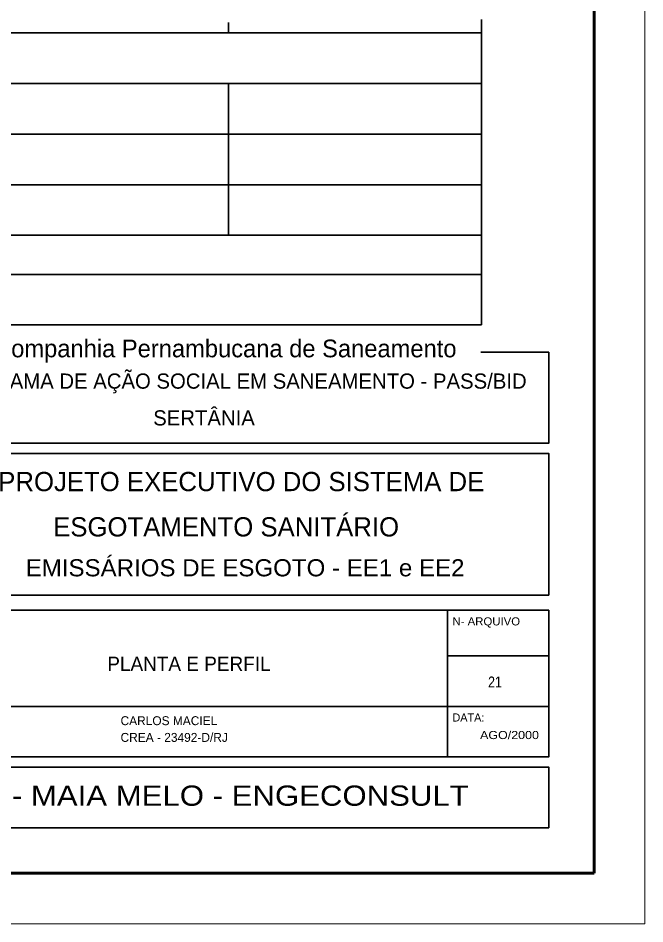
# Model space of a CAD drawing. Extents: x 949 to 2631, y -1701 to -513.
# Drawn here: x 2383.4 to 2630.9, y -1700.7 to -1342.6 of the extents above; entities that cross this region are included whole.
import ezdxf

# ---------------------------------------------------------------- set-up
doc = ezdxf.new("R2010")
doc.units = 0
doc.header["$LTSCALE"] = 1.2
for name, color, linetype, lineweight in [('10', 7, 'Continuous', 13), ('11', 7, 'Continuous', 13), ('2', 7, 'Continuous', 13), ('5', 7, 'Continuous', 13), ('6', 7, 'Continuous', 60), ('7', 7, 'Continuous', 35)]:
    doc.layers.add(name, color=color, linetype=linetype, lineweight=lineweight)

msp = doc.modelspace()

# ---------------------------------------------------------------- linework, layer by layer
at = {"layer": '10', "lineweight": 35}
for p, q in [((2552.926, -1634.728), (2552.926, -1576.728)), ((2592.926, -1594.728), (2552.926, -1594.728)), ((2344.926, -1614.728), (2592.926, -1614.728))]:
    msp.add_line(p, q, dxfattribs=at)
at = {"layer": '11', "lineweight": 35}
msp.add_lwpolyline([(2566.158, -1474.728), (2592.926, -1474.728), (2592.926, -1510.728), (2344.926, -1510.728), (2344.926, -1474.728)], dxfattribs=at)
for points in [[(2344.926, -1570.728), (2592.926, -1570.728), (2592.926, -1514.728), (2344.926, -1514.728)], [(2344.926, -1576.728), (2344.926, -1634.728), (2592.926, -1634.728), (2592.926, -1576.728)], [(2260.926, -1638.728), (2592.926, -1638.728), (2592.926, -1662.728), (2260.926, -1662.728)]]:
    msp.add_lwpolyline(points, close=True, dxfattribs=at)
at = {"layer": '2'}
msp.add_line((2630.926, -512.728), (2630.926, -1700.728), dxfattribs=at)
at = {"layer": '5'}
for q in [(2623.017, -1700.728), (2630.926, -1700.728), (2630.926, -1700.728)]:
    msp.add_line((948.926, -1700.728), q, dxfattribs=at)
msp.add_lwpolyline([(948.926, -1700.728), (2630.926, -1700.728), (948.926, -1700.728)], dxfattribs=at)
at = {"layer": '6'}
for p, q in [((2610.926, -532.728), (2610.926, -1680.728)), ((2610.926, -1680.728), (998.926, -1680.728))]:
    msp.add_line(p, q, dxfattribs=at)
at = {"layer": '7'}
for p, q in [((2466.405, -1344.336), (2466.405, -1348.501)), ((2566.405, -1343.129), (2566.405, -1463.951)), ((2566.405, -1343.129), (2566.405, -1463.951)), ((1064.486, -1348.501), (2566.405, -1348.501)), ((1064.486, -1368.501), (2566.405, -1368.501)), ((2066.396, -1368.501), (2566.405, -1368.501)), ((2466.405, -1368.501), (2466.405, -1428.501)), ((1064.486, -1388.501), (2566.405, -1388.501)), ((1064.486, -1408.501), (2566.405, -1408.501)), ((1064.486, -1428.501), (2566.405, -1428.501)), ((1064.486, -1443.951), (2566.405, -1443.951)), ((1064.486, -1463.951), (2566.405, -1463.951))]:
    msp.add_line(p, q, dxfattribs=at)

# ---------------------------------------------------------------- texts
at = {"layer": '10'}
for s, height, p in [('Companhia Pernambucana de Saneamento', 7, (2373.865, -1476.728)), ('PROJETO EXECUTIVO DO SISTEMA DE', 7.6, (2375.503, -1529.652)), ('ESGOTAMENTO SANITÁRIO', 7.6, (2397.192, -1547.555)), ('PLANTA E PERFIL', 5.6, (2418.579, -1600.697)), ('CARLOS MACIEL', 3.52, (2423.818, -1622.155)), ('DATA:', 3.2, (2554.926, -1620.728)), ('CREA - 23492-D/RJ', 3.52, (2423.818, -1628.762))]:
    msp.add_text(s, height=height, dxfattribs=at).set_placement(p)
for s, height, width, p in [('EMISSÁRIOS DE ESGOTO - EE1 e EE2', 6.772, 1.05, (2386.351, -1563.328)), ('N- ARQUIVO', 3.2, 1.05, (2554.926, -1582.728)), ('21', 4.3, 0.85, (2568.996, -1607.236)), ('AGO/2000', 3.2, 1.15, (2565.829, -1627.661)), ('ECOPLAN - MAIA MELO - ENGECONSULT', 8, 1.15, (2318.686, -1654.025))]:
    msp.add_text(s, height=height, dxfattribs=dict(at, width=width)).set_placement(p)
at = {"layer": '11'}
for s, p in [('PROGRAMA DE AÇÃO SOCIAL EM SANEAMENTO - PASS/BID', (2350.619, -1489.13)), ('SERTÂNIA', (2436.729, -1503.681))]:
    msp.add_text(s, height=6, dxfattribs=at).set_placement(p)

doc.saveas('drawing.dxf')
